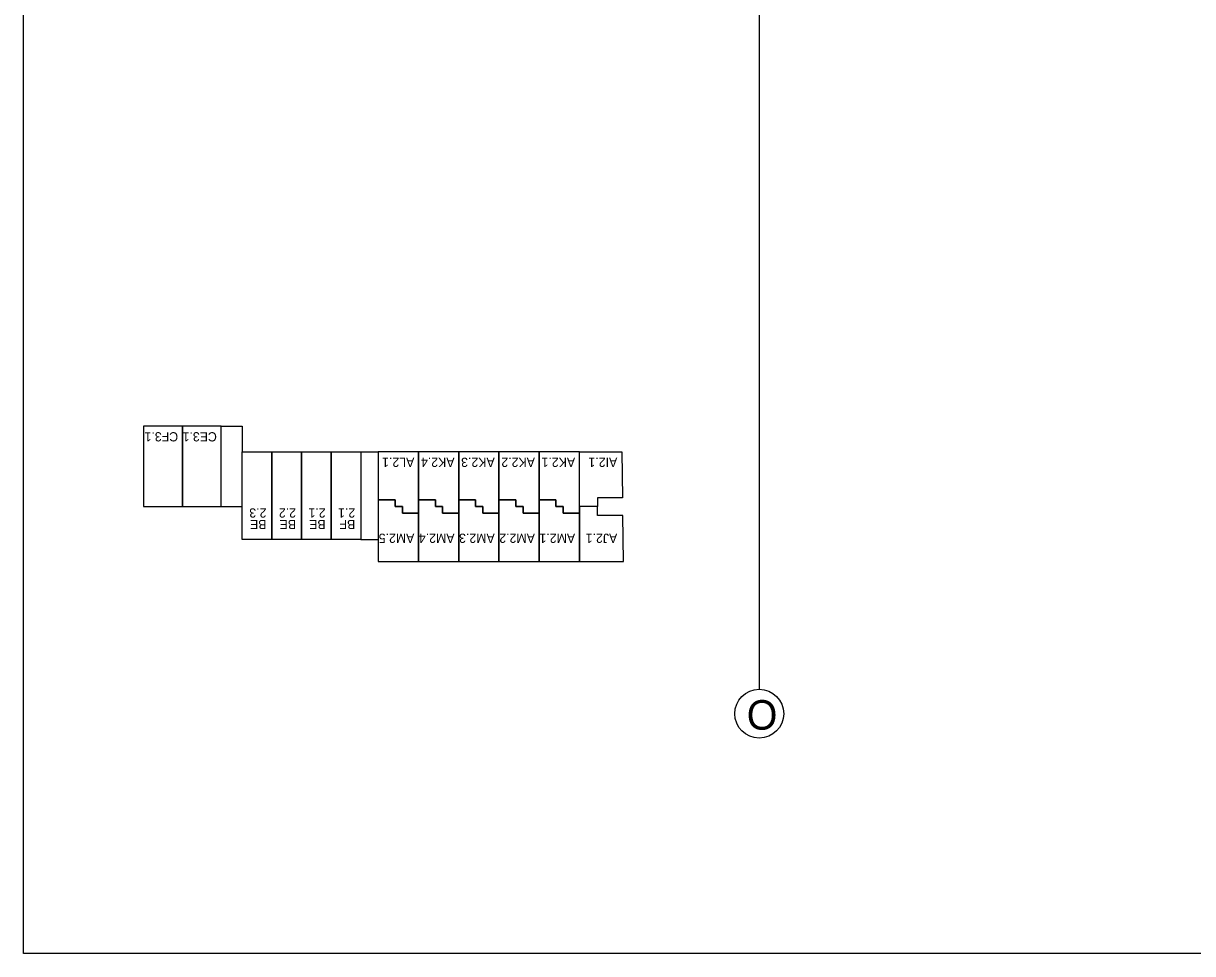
# Model space of a CAD drawing. Extents: x 1278 to 1356, y -253.7 to -224.
# Drawn here: x 1278.02 to 1290.7, y -253.66 to -243.57 of the extents above; entities that cross this region are included whole.
import ezdxf

# ---------------------------------------------------------------- set-up
doc = ezdxf.new("R2010")
doc.units = 0
for name, color, linetype in [('Level 40', 7, 'Continuous'), ('Level 62', 7, 'Continuous'), ('Level 70', 7, 'Continuous')]:
    doc.layers.add(name, color=color, linetype=linetype)

msp = doc.modelspace()

# ---------------------------------------------------------------- linework, layer by layer
at = {"layer": 'Level 40'}
for p, q in [((1280.161, -247.94), (1280.391, -247.94)), ((1280.391, -247.94), (1280.391, -248.218)), ((1281.676, -248.218), (1281.866, -248.218)), ((1280.161, -248.812), (1280.391, -248.812)), ((1281.676, -249.169), (1281.866, -249.169))]:
    msp.add_line(p, q, dxfattribs=at)
for points in [[(1279.741, -247.94), (1279.32, -247.94), (1279.32, -248.812), (1279.741, -248.812)], [(1280.161, -247.94), (1279.741, -247.94), (1279.741, -248.812), (1280.161, -248.812)], [(1280.712, -249.169), (1280.391, -249.169), (1280.391, -248.218), (1280.712, -248.218)], [(1281.033, -249.169), (1280.712, -249.169), (1280.712, -248.218), (1281.033, -248.218)], [(1281.355, -249.169), (1281.033, -249.169), (1281.033, -248.218), (1281.355, -248.218)], [(1281.676, -249.169), (1281.355, -249.169), (1281.355, -248.218), (1281.676, -248.218)], [(1282.302, -248.218), (1281.866, -248.218), (1281.866, -248.741), (1282.049, -248.741), (1282.049, -248.812), (1282.128, -248.812), (1282.128, -248.884), (1282.302, -248.884)], [(1282.738, -248.218), (1282.302, -248.218), (1282.302, -248.741), (1282.485, -248.741), (1282.485, -248.812), (1282.564, -248.812), (1282.564, -248.884), (1282.738, -248.884)], [(1283.175, -248.218), (1282.738, -248.218), (1282.738, -248.741), (1282.921, -248.741), (1282.921, -248.812), (1283, -248.812), (1283, -248.884), (1283.175, -248.884)], [(1283.611, -248.218), (1283.175, -248.218), (1283.175, -248.741), (1283.357, -248.741), (1283.357, -248.812), (1283.436, -248.812), (1283.436, -248.884), (1283.611, -248.884)], [(1284.047, -248.218), (1283.611, -248.218), (1283.611, -248.741), (1283.793, -248.741), (1283.793, -248.812), (1283.873, -248.812), (1283.873, -248.884), (1284.047, -248.884)], [(1284.509, -248.218), (1284.516, -248.717), (1284.245, -248.717), (1284.245, -248.812), (1284.047, -248.812), (1284.047, -248.218)], [(1281.866, -249.407), (1282.302, -249.407), (1282.302, -248.884), (1282.128, -248.884), (1282.128, -248.812), (1282.049, -248.812), (1282.049, -248.741), (1281.866, -248.741)], [(1282.302, -249.407), (1282.738, -249.407), (1282.738, -248.884), (1282.564, -248.884), (1282.564, -248.812), (1282.485, -248.812), (1282.485, -248.741), (1282.302, -248.741)], [(1282.738, -249.407), (1283.175, -249.407), (1283.175, -248.884), (1283, -248.884), (1283, -248.812), (1282.921, -248.812), (1282.921, -248.741), (1282.738, -248.741)], [(1283.175, -249.407), (1283.611, -249.407), (1283.611, -248.884), (1283.436, -248.884), (1283.436, -248.812), (1283.357, -248.812), (1283.357, -248.741), (1283.175, -248.741)], [(1283.611, -249.407), (1284.047, -249.407), (1284.047, -248.884), (1283.873, -248.884), (1283.873, -248.812), (1283.793, -248.812), (1283.793, -248.741), (1283.611, -248.741)], [(1284.245, -248.812), (1284.047, -248.812), (1284.047, -249.407), (1284.526, -249.407), (1284.519, -248.908), (1284.245, -248.908)]]:
    msp.add_lwpolyline(points, close=True, dxfattribs=at)
msp.add_circle((1285.998, -251.058), 0.265, dxfattribs=at)
at = {"layer": 'Level 62'}
msp.add_lwpolyline([(1355.966, -223.959), (1355.966, -253.659), (1278.016, -253.659), (1278.016, -223.959)], close=True, dxfattribs=at)
at = {"layer": 'Level 70'}
msp.add_line((1285.998, -225.567), (1285.998, -250.792), dxfattribs=at)

# ---------------------------------------------------------------- texts
at = {"layer": 'Level 40'}
for s, height, p in [('CF3.1', 0.1, (1279.695, -248.006)), ('CE3.1', 0.1, (1280.115, -248.006)), ('AL2.1', 0.1, (1282.257, -248.283)), ('AK2.4', 0.1, (1282.693, -248.283)), ('AK2.3', 0.1, (1283.129, -248.283)), ('AK2.2', 0.1, (1283.565, -248.283)), ('AK2.1', 0.1, (1284.001, -248.283)), ('AI2.1', 0.1, (1284.458, -248.283)), ('2.3', 0.1, (1280.653, -248.832)), ('2.2', 0.1, (1280.974, -248.832)), ('2.1', 0.1, (1281.295, -248.832)), ('2.1', 0.1, (1281.616, -248.832)), ('BE', 0.1, (1280.653, -248.957)), ('BE', 0.1, (1280.974, -248.957)), ('BE', 0.1, (1281.295, -248.957)), ('BF', 0.1, (1281.616, -248.957)), ('AM2.5', 0.1, (1282.257, -249.106)), ('AM2.4', 0.1, (1282.693, -249.106)), ('AM2.3', 0.1, (1283.129, -249.106)), ('AM2.2', 0.1, (1283.565, -249.106)), ('AM2.1', 0.1, (1284.001, -249.106)), ('AJ2.1', 0.1, (1284.458, -249.106)), ('O', 0.32, (1286.195, -250.911))]:
    msp.add_text(s, height=height, rotation=180, dxfattribs=at).set_placement(p)

doc.saveas('drawing.dxf')
